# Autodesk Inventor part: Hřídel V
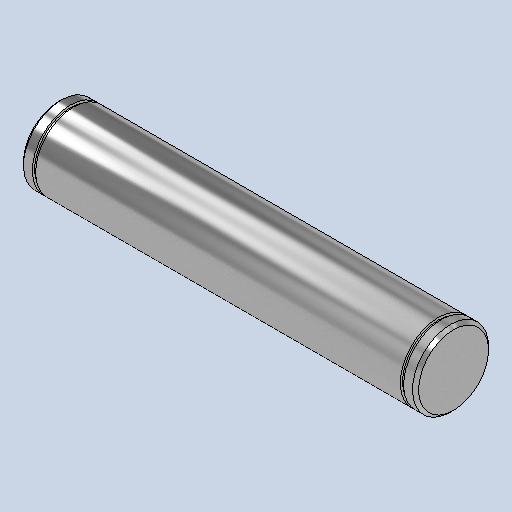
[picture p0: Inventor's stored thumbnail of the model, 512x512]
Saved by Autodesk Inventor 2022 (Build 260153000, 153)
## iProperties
Created: 2025-05
Part Number: Hřídel V
Material: Všeobecné
Document SubType Name: Modeling
Designer: jbart
Density: 1 g/cm^3
Appearance: Broušená
Mass: 508.914 g
Surface Area: 452.629 cm^2
Volume: 508.914 cm^3
Author: jbart
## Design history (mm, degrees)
sketch "Náčrt1"
  geometry: L1 (0, 0)-(260, 0); L2 (0, 0)-(0, 25); L3 (0, 25)-(7.85, 25); L4 (7.85, 25)-(7.85, 23.5); L5 (7.85, 23.5)-(10, 23.5); L6 (10, 23.5)-(10, 25); L7 (10, 25)-(250, 25); L8 (250, 25)-(250, 23.5); L9 (250, 23.5)-(252.15, 23.5); L10 (252.15, 23.5)-(252.15, 25); L11 (252.15, 25)-(260, 25); L12 (260, 25)-(260, 0); L13 (130, 0)-(130, 25)
  constraints: 26 end point, 8 perpendicular, 6 point on line, 2 midpoint, 1 collinear, 1 horizontal, 1 vertical
  dimensions: "d0" = 260 distance of L1.start L1.end; "d1" = 50 diameter of L3 L1; "d2" = 47 diameter of L5 L1; "d3" = 2.15 distance of L4.end L5.end; "d4" = 120 distance between parallel lines of L13 L6; "d6" = 120 distance between parallel lines of L13 L8
revolve "Rotace1" sketch "Náčrt1" stored, may be unused: angle "d7" = 90 deg
chamfer "Zkosení1" distance "d8" = 2; stored, may be unused: second distance "d9" = 2, angle "d10" = 45 deg
node "Těleso1"
